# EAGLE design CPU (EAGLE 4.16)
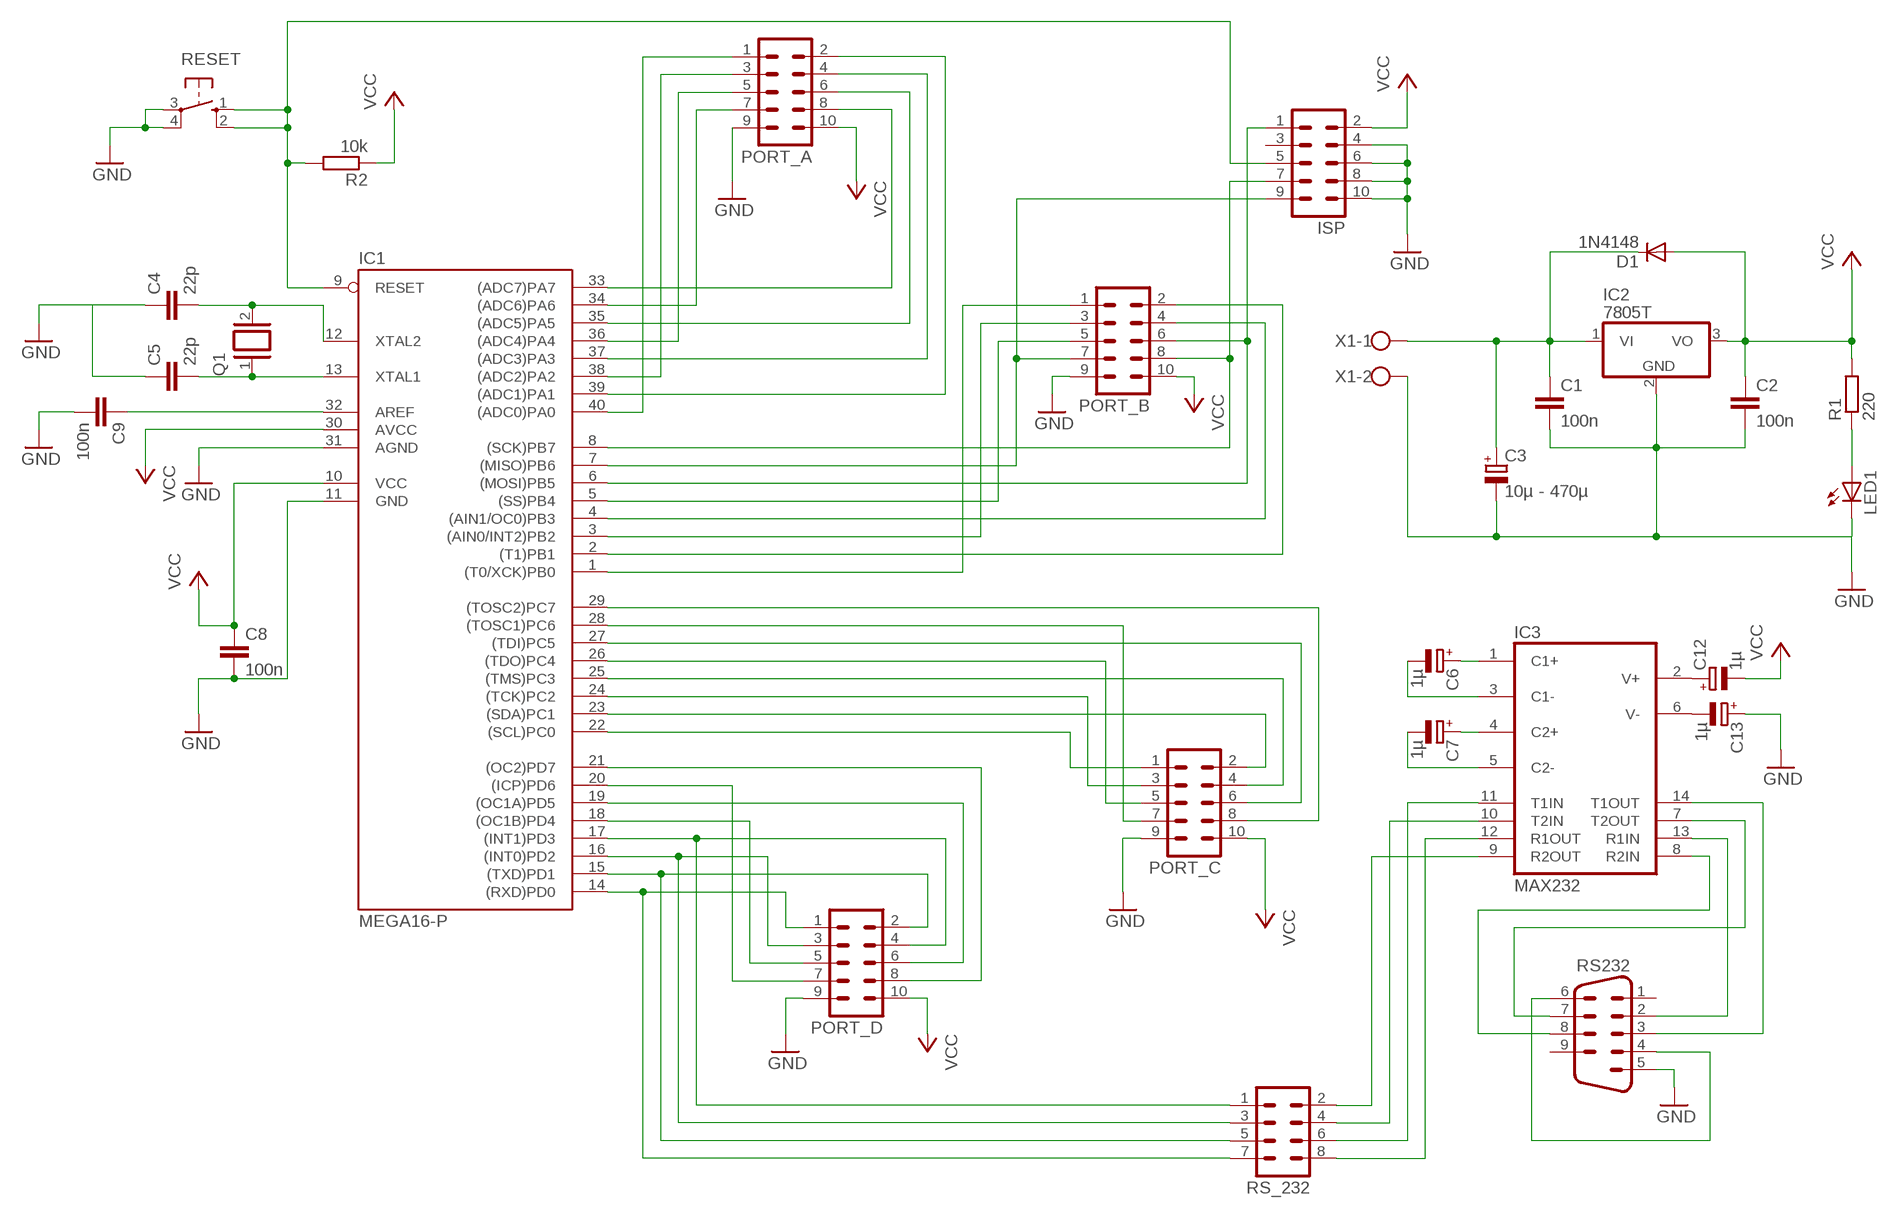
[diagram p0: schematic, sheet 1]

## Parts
C1  100n  C7.5/5  [C7.5B5]
C2  100n  C7.5/5  [C7.5B5]
C3  10µ - 470µ  CPOL-EUE5-10.5  [E5-10,5]
C4  22p  C5/3  [C5B3]
C5  22p  C5/3  [C5B3]
C6  1µ  CPOL-EUE3.5-8  [E3,5-8]
C7  1µ  CPOL-EUE3.5-8  [E3,5-8]
C8  100n  C2.5/4  [C2.5-4]
C9  100n  C5/3  [C5B3]
C12  1µ  CPOL-EUE3.5-8  [E3,5-8]
C13  1µ  CPOL-EUE3.5-8  [E3,5-8]
D1  1N4148  [DO35-10]
IC1  MEGA16-P  [DIL40]
IC2  7805T  [TO220H]
IC3  MAX232  [DIL16]
ISP  ML10  [ML10]
LED1  LED3MM  [LED3MM]
PORT_A  ML10  [ML10]
PORT_B  ML10  [ML10]
PORT_C  ML10  [ML10]
PORT_D  ML10  [ML10]
Q1  XTAL  [Q]
R1  220  R-EU_0207/10  [0207/10]
R2  10k  R-EU_0207/10  [0207/10]
RESET  10-XX  [B3F-10XX]
RS232  M09H  [M09H]
RS_232  MA04-2  [MA04-2]
X1  W237-102  [W237-102]

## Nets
GND: C1.2 C2.2 C3.- C4.1 C5.1 C8.2 C9.2 C13.+ IC1.11(GND) IC1.31(AGND) IC2.2(GND) ISP.4 ISP.6 ISP.8 ISP.10 LED1.K(C) PORT_A.9 PORT_B.9 PORT_C.9 PORT_D.9 RESET.3(P) RESET.4(P1) RS232.5 X1.2
ISP: IC1.7((MISO)PB6) ISP.9 PORT_B.7
N$1: C1.1 C3.+ D1.C IC2.1(VI) X1.1
N$5: LED1.A R1.1
N$6: IC1.40((ADC0)PA0) PORT_A.1
N$7: IC1.39((ADC1)PA1) PORT_A.2
N$8: IC1.37((ADC3)PA3) PORT_A.4
N$9: IC1.35((ADC5)PA5) PORT_A.6
N$10: IC1.33((ADC7)PA7) PORT_A.8
N$11: IC3.10(T2IN) RS_232.4
N$12: IC1.36((ADC4)PA4) PORT_A.5
N$13: IC1.34((ADC6)PA6) PORT_A.7
N$14: IC1.1((T0/XCK)PB0) PORT_B.1
N$15: IC1.2((T1)PB1) PORT_B.2
N$16: IC1.4((AIN1/OC0)PB3) PORT_B.4
N$17: IC1.6((MOSI)PB5) ISP.1 PORT_B.6
N$18: IC1.8((SCK)PB7) ISP.7 PORT_B.8
N$19: IC1.3((AIN0/INT2)PB2) PORT_B.3
N$20: IC1.5((SS)PB4) PORT_B.5
N$21: IC1.38((ADC2)PA2) PORT_A.3
N$22: IC1.22((SCL)PC0) PORT_C.1
N$23: IC1.23((SDA)PC1) PORT_C.2
N$24: IC1.24((TCK)PC2) PORT_C.3
N$25: IC1.25((TMS)PC3) PORT_C.4
N$26: IC1.26((TDO)PC4) PORT_C.5
N$27: IC1.27((TDI)PC5) PORT_C.6
N$28: IC1.28((TOSC1)PC6) PORT_C.7
N$29: IC1.29((TOSC2)PC7) PORT_C.8
N$30: IC1.14((RXD)PD0) PORT_D.1 RS_232.7
N$31: IC1.15((TXD)PD1) PORT_D.2 RS_232.5
N$32: IC1.16((INT0)PD2) PORT_D.3 RS_232.3
N$33: IC1.17((INT1)PD3) PORT_D.4 RS_232.1
N$34: IC1.18((OC1B)PD4) PORT_D.5
N$35: IC1.19((OC1A)PD5) PORT_D.6
N$36: IC1.20((ICP)PD6) PORT_D.7
N$37: IC1.21((OC2)PD7) PORT_D.8
N$38: IC3.9(R2OUT) RS_232.2
N$39: C5.2 IC1.13(XTAL1) Q1.1
N$40: C4.2 IC1.12(XTAL2) Q1.2
N$42: C12.+ IC3.2(V+)
N$43: C13.- IC3.6(V-)
N$44: RS232.4 RS232.6
N$45: IC3.12(R1OUT) RS_232.8
N$46: IC3.11(T1IN) RS_232.6
N$47: IC3.7(T2OUT) RS232.7
N$48: IC3.8(R2IN) RS232.8
N$49: IC1.9(RESET) ISP.5 R2.2 RESET.1(S) RESET.2(S1)
N$53: C9.1 IC1.32(AREF)
N$201: C6.- IC3.3(C1-)
N$202: C6.+ IC3.1(C1+)
N$203: C7.- IC3.5(C2-)
N$204: C7.+ IC3.4(C2+)
N$205: IC3.14(T1OUT) RS232.3
N$206: IC3.13(R1IN) RS232.2
VCC: C2.1 C8.1 C12.- D1.A IC1.10(VCC) IC1.30(AVCC) IC2.3(VO) ISP.2 PORT_A.10 PORT_B.10 PORT_C.10 PORT_D.10 R1.2 R2.1
Unconnected: ISP.3 RS232.1 RS232.9

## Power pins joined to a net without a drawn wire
GND: IC3.15(GND)
VCC: IC3.16(VCC)

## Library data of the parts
C1 C2 C4 C5 C8 C9 = capacitor-wima:C: CAPACITOR
C3 C6 C7 C12 C13 = rcl:CPOL-EU: POLARIZED CAPACITOR, European symbol
D1 = diode:1N4148: DIODE
IC1 = atmel:MEGA16-P: MICROCONTROLLER 16 Kbytes FLASH 1 kbytes SRAM 512 bytes EEPROM USART 8-channel 10 bit ADC Source: avr.lbr
IC2 = linear:78*: Positive VOLTAGE REGULATOR Source: http://cache.national.com/ds/LM/LM78L05.pdf http://www.fairchildsemi.com/ds/LM/LM7805.pdf
IC3 = maxim:MAX232: RS232 TRANSEIVER
ISP PORT_A PORT_B PORT_C PORT_D = con-harting-ml:ML10: HARTING
LED1 = led:LED: LED
Q1 = special:XTAL: CRYSTAL
R1 R2 = rcl:R-EU_: RESISTOR, European symbol
RESET = switch-omron:10-XX: OMRON SWITCH
RS232 = con-subd:M09: SUB-D
RS_232 = con-lstb:MA04-2: PIN HEADER
X1 = con-wago-500:W237-102: WAGO SCREW CLAMP

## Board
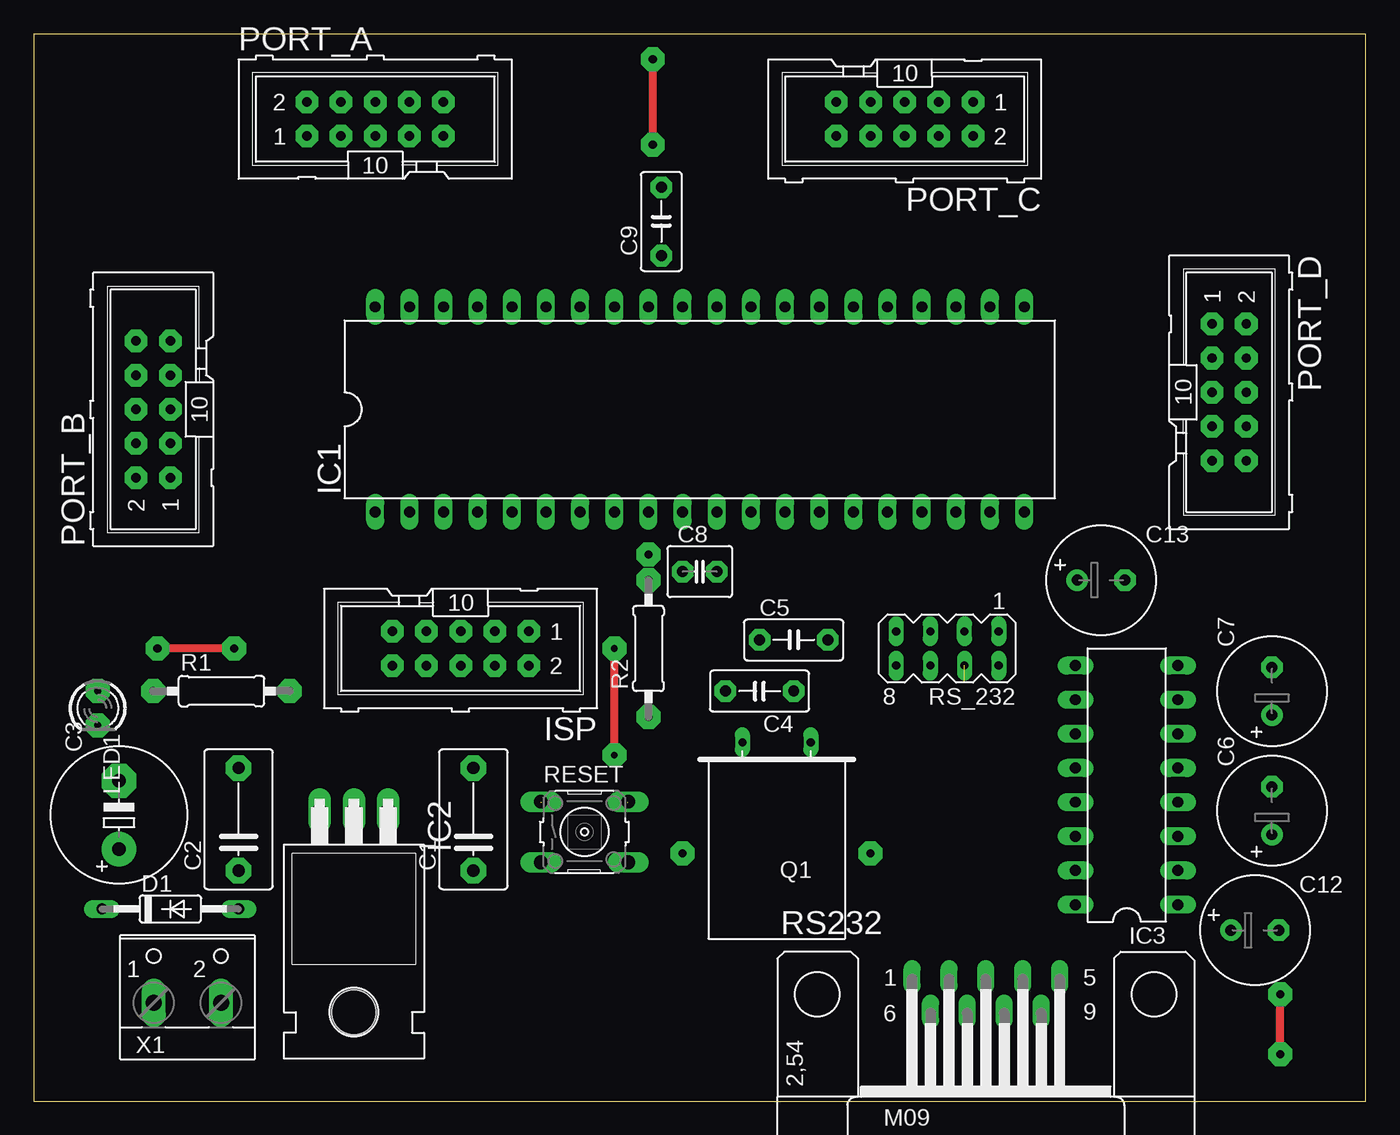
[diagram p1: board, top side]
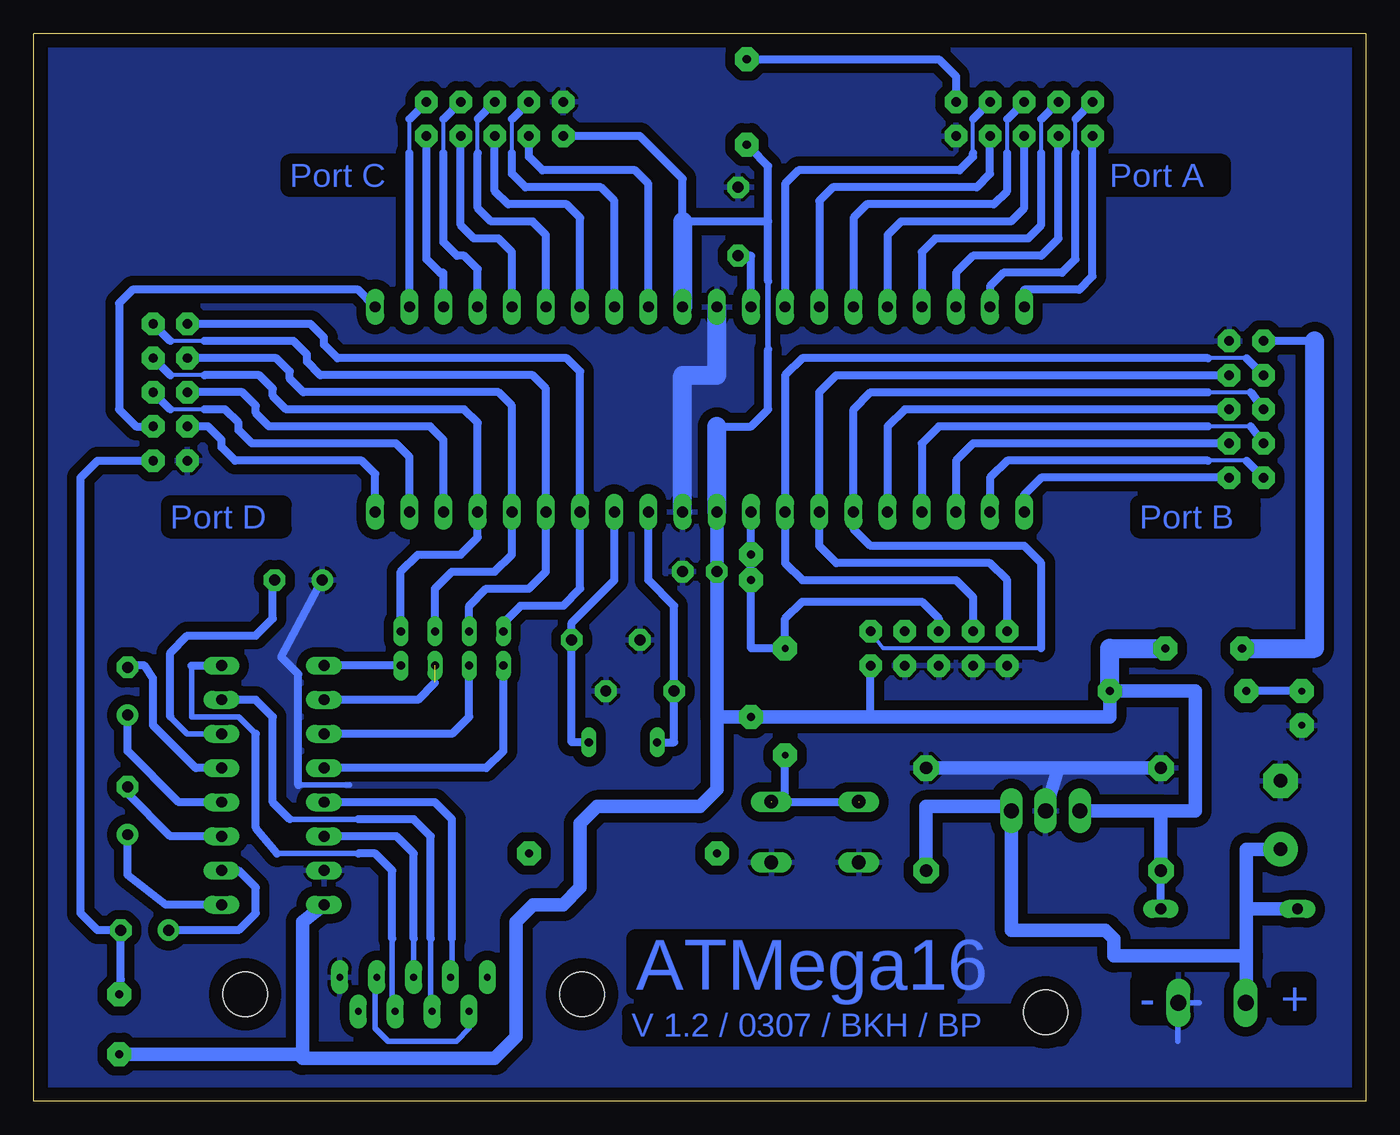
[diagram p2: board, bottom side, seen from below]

Size 99.06 x 79.38 mm. Coordinates in mm from the lower left corner, seen from the top.
Outline: 0,0 99.06,0 99.06,79.38 0,79.38 0,0
Copper layers (1*16): Top 0.035mm / dielectric 1.5mm / Bottom 0.035mm
Design rules "default": minimum track width 10mil, minimum drill 24mil, track to track 28mil, track to pad 28mil, pad to pad 10mil, via to via 10mil, smd to smd 8mil, copper to edge 40mil, drill to drill 8mil, minimum pad ring 10mil, minimum via ring 8mil, stop-mask expansion 4mil, vias tented up to drill 0mil, thermal gap 10mil

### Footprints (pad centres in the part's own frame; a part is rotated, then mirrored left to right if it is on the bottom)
C7.5B5 = drill 0.914 pad 1.905 octagon: 1 -3.81,0; 2 3.81,0
E5-10,5 = drill 1.016 pad 2.54 round: + -2.54,0 | drill 1.016 pad 2.54 octagon: - 2.54,0
C5B3 = drill 0.813 pad 1.6 octagon: 1 -2.54,0; 2 2.54,0
E3,5-8 = drill 0.813 pad 1.6 round: + -1.778,0 | drill 0.813 pad 1.6 octagon: - 1.778,0
C2.5-4 = drill 0.813 pad 1.6 octagon: 1 -1.27,0; 2 1.27,0
DO35-10 = drill 0.813 long: A 5.08,0; C -5.08,0
DIL40 = drill 0.813 long: 1 -24.13,-7.62; 2 -21.59,-7.62; 3 -19.05,-7.62; 4 -16.51,-7.62; 5 -13.97,-7.62; 6 -11.43,-7.62; 7 -8.89,-7.62; 8 -6.35,-7.62; 9 -3.81,-7.62; 10 -1.27,-7.62; 11 1.27,-7.62; 12 3.81,-7.62; 13 6.35,-7.62; 14 8.89,-7.62; 15 11.43,-7.62; 16 13.97,-7.62; 17 16.51,-7.62; 18 19.05,-7.62; 19 21.59,-7.62; 20 24.13,-7.62; 21 24.13,7.62; 22 21.59,7.62; 23 19.05,7.62; 24 16.51,7.62; 25 13.97,7.62; 26 11.43,7.62; 27 8.89,7.62; 28 6.35,7.62; 29 3.81,7.62; 30 1.27,7.62; 31 -1.27,7.62; 32 -3.81,7.62; 33 -6.35,7.62; 34 -8.89,7.62; 35 -11.43,7.62; 36 -13.97,7.62; 37 -16.51,7.62; 38 -19.05,7.62; 39 -21.59,7.62; 40 -24.13,7.62
TO220H = drill 1.118 long: 1 -2.54,-10.16; 2 0,-10.16; 3 2.54,-10.16 | hole 3.302: 0,4.826
DIL16 = drill 0.813 long: 1 -8.89,-3.81; 2 -6.35,-3.81; 3 -3.81,-3.81; 4 -1.27,-3.81; 5 1.27,-3.81; 6 3.81,-3.81; 7 6.35,-3.81; 8 8.89,-3.81; 9 8.89,3.81; 10 6.35,3.81; 11 3.81,3.81; 12 1.27,3.81; 13 -1.27,3.81; 14 -3.81,3.81; 15 -6.35,3.81; 16 -8.89,3.81
ML10 = drill 0.7 pad 1.676 octagon: 1 -5.08,-1.27; 2 -5.08,1.27; 3 -2.54,-1.27; 4 -2.54,1.27; 5 0,-1.27; 6 0,1.27; 7 2.54,-1.27; 8 2.54,1.27; 9 5.08,-1.27; 10 5.08,1.27
LED3MM = drill 0.5 pad 1.778 octagon: A -1.27,0; K 1.27,0
Q = drill 0.61 long: 1 -2.54,-7.62; 2 2.54,-7.62
0207/10 = drill 0.6 pad 1.778 octagon: 1 -5.08,0; 2 5.08,0
B3F-10XX = drill 1.016 long: 1 -3.251,2.261; 2 3.251,2.261; 3 -3.251,-2.261; 4 3.251,-2.261
M09H = drill 0.5 pad 1.27 long: 1 -5.486,1.27; 2 -2.743,1.27; 3 0,1.27; 4 2.743,1.27; 5 5.486,1.27; 6 -4.115,-1.27; 7 -1.372,-1.27; 8 1.372,-1.27; 9 4.115,-1.27 | hole 3.302: 12.522,0; -12.522,0
MA04-2 = drill 0.6 long: 1 -3.81,-1.27; 2 -3.81,1.27; 3 -1.27,-1.27; 4 -1.27,1.27; 5 1.27,-1.27; 6 1.27,1.27; 7 3.81,-1.27; 8 3.81,1.27
W237-102 = drill 1.194 long: 1 -2.5,-1.27; 2 2.5,-1.27

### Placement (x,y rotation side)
C1  32.7,20.95 90 top
C2  15.24,20.95 90 top
C3  6.35,21.27 90 top
C4  53.98,30.48 180 top
C5  56.52,34.29 0 top
C6  92.08,21.59 90 top
C7  92.08,30.48 90 top
C8  49.53,39.37 0 top
C9  46.67,65.41 90 top
C12  90.81,12.7 0 top
C13  79.38,38.73 0 top
D1  10.16,14.29 0 top
IC1  49.53,51.44 0 top
IC2  23.81,11.43 180 top
IC3  81.28,23.5 90 top
ISP  31.75,33.66 180 top
LED1  4.76,29.21 270 top
PORT_A  25.4,73.03 0 top
PORT_B  8.89,51.44 90 top
PORT_C  64.77,73.03 180 top
PORT_D  88.9,52.7 270 top
Q1  55.24,19.05 180 top
R1  13.97,30.48 0 top
R2  45.72,33.66 90 top
RESET  40.96,20 0 top
RS232  70.8,7.94 0 top
RS_232  67.94,33.66 180 top
X1  11.43,8.57 0 top

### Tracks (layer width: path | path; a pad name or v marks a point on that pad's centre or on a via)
GND
  Bottom 0.406: 75.56,23.5 79.38,23.5 | 12.38,7.3 X1.2 13.97,7.3 13.97,4.45
  Bottom 0.61: C13.+ 80.64,33.02 79.38,31.75 79.38,23.5
  Bottom 1.016: 22.86,24.77 IC2.2 | 22.86,24.77 C1.2 | C2.2 22.86,24.77
  Bottom 1.422: IC1.31 48.26,53.98 50.8,53.98 IC1.11
  pour Bottom: 0,0.95 98.11,0.95 98.11,81.6 0,81.6
ISP
  Bottom 0.61: ISP.9 26.67,38.73 27.94,40.01 39.37,40.01 40.64,41.27 IC1.7 40.64,52.7 39.37,53.98 PORT_B.7
N$1
  Bottom 1.016: C1.1 32.7,21.91 26.67,21.91 IC2.1 26.35,12.7 19.37,12.7 18.73,12.06 18.73,10.79 8.89,10.79 | C3.+ 8.89,18.73 8.89,14.29 | 8.89,10.79 8.89,14.29 | X1.1 8.89,7.34 8.89,10.79 | 8.89,14.29 D1.C
N$3  (via drill 0.5 pad 1.78)
  other vias: 43.18,25.72
N$4  (via drill 0.6 pad 1.78)
  other vias: 48.26,18.41
N$5
  Bottom 0.61: LED1.A R1.1
N$6
  Bottom 0.61: PORT_A.1 20.32,61.33 21.32,60.33 25.4,60.33 IC1.40
N$7
  Bottom 0.305: 21.59,70.48 21.59,73.03
  Bottom 0.61: 21.59,73.03 PORT_A.2 | 21.59,70.48 21.59,62.59 22.59,61.59 26.94,61.59 27.94,60.59 IC1.39
N$8
  Bottom 0.305: 24.13,70.48 24.13,73.03
  Bottom 0.61: 24.13,73.03 PORT_A.4 | 24.13,70.48 24.13,65.14 25.13,64.14 32.02,64.14 33.02,63.13 IC1.37
N$9
  Bottom 0.305: 26.67,70.48 26.67,73.03
  Bottom 0.61: 26.67,73.03 PORT_A.6 | 26.67,70.48 26.67,67.67 27.67,66.67 37.1,66.67 38.1,65.67 IC1.35
N$10
  Bottom 0.305: 29.21,70.48 29.21,73.03
  Bottom 0.61: 29.21,73.03 PORT_A.8 | 29.21,70.48 29.21,70.22 30.21,69.22 42.18,69.22 43.18,68.22 IC1.33
N$11  (1 unrouted)
  Bottom 0.61: 69.22,31.11 70.48,29.84 IC3.10
N$12
  Bottom 0.61: PORT_A.5 25.4,66.41 26.4,65.41 34.56,65.41 35.56,64.41 IC1.36
N$13
  Bottom 0.61: PORT_A.7 27.94,68.94 28.94,67.94 39.64,67.94 40.64,66.94 IC1.34
N$14
  Bottom 0.61: PORT_B.1 24.13,46.35 25.4,45.09 IC1.1
N$15
  Bottom 0.305: 8.89,47.62 11.75,47.62
  Bottom 0.61: PORT_B.2 8.89,47.62 | IC1.2 27.94,46.35 26.67,47.62 11.75,47.62
N$16
  Bottom 0.305: 8.57,50.16 11.75,50.16
  Bottom 0.61: PORT_B.4 8.57,50.16 | IC1.4 33.02,48.9 31.75,50.16 11.75,50.16
N$17
  Bottom 0.305: 11.75,52.7 8.57,52.7 | 24.13,33.66 35.88,33.66 ISP.1
  Bottom 0.61: 8.57,52.7 PORT_B.6 | 24.13,33.66 24.13,40.01 25.4,41.27 36.83,41.27 38.1,42.55 IC1.6 38.1,51.44 36.83,52.7 11.75,52.7
N$18
  Bottom 0.305: 8.89,55.24 11.75,55.24
  Bottom 0.61: PORT_B.8 8.89,55.24 | ISP.7 29.21,37.47 30.48,38.73 41.91,38.73 43.18,40.01 IC1.8 43.18,53.98 41.91,55.24 11.75,55.24
N$19
  Bottom 0.61: IC1.3 30.48,47.62 29.21,48.9 PORT_B.3
N$20
  Bottom 0.61: IC1.5 35.56,50.16 34.29,51.44 PORT_B.5
N$21
  Bottom 0.61: IC1.38 30.48,61.59 29.21,62.87 24.13,62.87 22.86,64.14 PORT_A.3
N$22
  Bottom 0.305: 71.12,70.48 71.12,73.03
  Bottom 0.61: IC1.22 71.12,70.48 | 71.12,73.03 PORT_C.1
N$23
  Bottom 0.61: IC1.23 68.58,61.59 68.85,61.59 69.85,62.59 PORT_C.2
N$24
  Bottom 0.305: 68.58,70.48 68.58,73.03
  Bottom 0.61: IC1.24 66.04,61.87 67.04,62.87 67.58,62.87 68.58,63.87 68.58,70.48 | 68.58,73.03 PORT_C.3
N$25
  Bottom 0.61: IC1.25 63.5,63.13 64.5,64.14 66.31,64.14 67.31,65.14 PORT_C.4
N$26
  Bottom 0.305: 66.04,70.48 66.04,73.03
  Bottom 0.61: IC1.26 60.96,64.41 61.96,65.41 65.04,65.41 66.04,66.41 66.04,70.48 | 66.04,73.03 PORT_C.5
N$27
  Bottom 0.61: IC1.27 58.42,65.67 59.42,66.67 63.77,66.67 64.77,67.67 PORT_C.6
N$28
  Bottom 0.305: 63.5,70.48 63.5,73.03
  Bottom 0.61: IC1.28 55.88,66.94 56.88,67.94 62.5,67.94 63.5,68.94 63.5,70.48 | 63.5,73.03 PORT_C.7
N$29
  Bottom 0.61: IC1.29 53.34,68.22 54.34,69.22 61.23,69.22 62.23,70.22 PORT_C.8
N$30
  Bottom 0.61: PORT_D.1 78.47,57.78 77.47,56.78 77.47,56.24 76.47,55.24 59.42,55.24 58.42,54.24 IC1.14 58.42,38.1 59.69,36.83 62.87,36.83 64.14,35.56 RS_232.7
N$31
  Bottom 0.305: 86.36,56.52 88.9,56.52
  Bottom 0.61: 86.36,56.52 79.74,56.52 78.74,55.52 78.74,54.98 77.74,53.98 61.96,53.98 60.96,52.98 IC1.15 60.96,39.37 62.23,38.1 65.41,38.1 66.67,36.83 RS_232.5 | 88.9,56.52 PORT_D.2
N$32
  Bottom 0.61: PORT_D.3 81.01,55.24 80.01,54.24 80.01,53.7 79.01,52.7 64.5,52.7 63.5,51.7 IC1.16 63.5,40.64 64.77,39.37 67.94,39.37 69.22,38.1 RS_232.3
N$33
  Bottom 0.305: 86.36,53.98 88.9,53.98
  Bottom 0.61: 86.36,53.98 82.28,53.98 81.28,52.98 81.28,52.44 80.28,51.44 67.04,51.44 66.04,50.44 IC1.17 66.04,41.91 67.31,40.64 70.48,40.64 71.75,39.37 RS_232.1 | 88.9,53.98 PORT_D.4
N$34
  Bottom 0.61: IC1.18 68.58,49.16 69.58,50.16 81.55,50.16 82.55,51.16 82.55,51.7 83.55,52.7 PORT_D.5
N$35
  Bottom 0.305: 86.36,51.44 88.9,51.44
  Bottom 0.61: IC1.19 71.12,47.9 72.12,48.9 82.82,48.9 83.82,49.9 83.82,50.44 84.82,51.44 86.36,51.44 | 88.9,51.44 PORT_D.6
N$36
  Bottom 0.61: IC1.20 73.66,46.62 74.66,47.62 84.09,47.62 85.09,48.62 85.09,49.16 86.09,50.16 PORT_D.7
N$37
  Bottom 0.61: IC1.21 74.93,60.33 91.71,60.33 92.71,59.33 92.71,51.44 91.44,50.16 PORT_D.8
N$38
  Bottom 0.61: RS_232.2 IC3.9
N$39
  Bottom 0.61: Q1.1 59.05,26.67 C5.2 59.05,35.56 55.88,38.73 IC1.13
N$40
  Bottom 0.61: Q1.2 51.44,26.67 C4.2 51.44,36.83 53.34,38.73 IC1.12
N$41  (via drill 0.6 pad 1.78)
  other vias: 62.23,18.41
N$42
  Bottom 0.61: IC3.2 83.82,17.14 82.55,15.88 82.55,13.97 83.82,12.7 C12.+
N$43
  Bottom 0.406: IC3.6 87.63,27.3 88.9,28.57
  Bottom 0.61: 88.9,28.57 88.9,33.34 87.63,34.61 82.55,34.61 81.28,35.88 81.28,38.73 C13.-
N$44
  Bottom 0.406: 73.66,9.09 73.66,5.4 72.71,4.45 67.63,4.45 66.67,5.4 66.67,6.67
  Bottom 0.61: 73.66,9.09 RS232.4 | 66.67,6.67 RS232.6
N$45
  Bottom 0.61: IC3.12 65.41,24.77 64.14,26.04 RS_232.8
N$46
  Bottom 0.61: RS_232.6 66.67,28.57 67.94,27.3 IC3.11
N$47
  Bottom 0.406: 74.93,20.95 80.01,20.95 | 69.53,6.67 69.53,12.06
  Bottom 0.61: 74.93,20.95 70.8,20.95 69.53,19.68 69.53,12.06 | 80.01,20.95 81.28,22.23 81.28,28.57 82.55,29.84 IC3.7 | RS232.7 69.53,6.67
N$48
  Bottom 0.406: 87.31,32.38 87.31,28.57 83.82,28.57 82.55,27.3 | 74.93,18.41 80.96,18.41 | 72.39,6.67 72.39,12.06
  Bottom 0.61: 87.31,32.38 IC3.8 | 82.55,27.3 82.55,20.32 80.96,18.41 | 74.93,18.41 73.66,18.41 72.39,17.14 72.39,12.06 | RS232.8 72.39,6.67
N$49  (via drill 0.5 pad 1.78, 0.6 pad 1.78)  (2 unrouted)
  Top 0.61: v43.18,25.72 v43.18,33.66
  Bottom 0.61: ISP.5 31.75,35.88 33.02,37.15 41.91,37.15 43.18,35.88 v43.18,33.66 45.72,33.66 R2.2 v45.72,40.64 IC1.9 | 43.18,22.23 v43.18,25.72 | 43.18,22.23 44.17,22.23 | 37.74,22.23 43.18,22.23
N$53
  Bottom 0.61: IC1.32 45.72,62.87 C9.1
N$201
  Bottom 0.61: IC3.3 88.9,19.68 92.08,22.86 C6.- 92.08,23.5
N$202
  Bottom 0.61: IC3.1 89.22,14.61 92.08,16.83 C6.+
N$203
  Bottom 0.61: C7.- 92.08,32.38 90.81,32.38 90.17,31.43 90.17,27.94 87,24.77 IC3.5
N$204
  Bottom 0.61: IC3.4 88.27,22.23 92.08,26.04 C7.+
N$205
  Bottom 0.406: RS232.3 70.8,12.06
  Bottom 0.61: RS232.3 70.48,9.21 | IC3.14 72.07,19.68 70.8,18.41 70.8,12.06
N$206
  Bottom 0.406: 67.94,9.21 67.94,12.06
  Bottom 0.61: IC3.13 69.22,22.23 67.94,20.95 67.94,12.06 | RS232.2 67.94,9.21
VCC  (via drill 0.6 pad 1.78)
  Top 0.61: v14.92,33.66 v9.21,33.66 | v92.71,3.49 v92.71,7.94 | v46.04,71.12 v46.04,77.47
  Bottom 0.406: 44.45,55.88 44.45,60.96 | 79.06,3.17 79.06,3.49
  Bottom 0.61: C8.1 IC1.10 | D1.A C2.1 | 48.26,50.16 45.72,50.16 44.45,51.44 44.45,55.88 | 44.45,60.96 44.45,65.41 | 44.45,65.41 50.8,65.41 50.8,68.58 53.98,71.75 PORT_C.10 | 3.81,56.52 PORT_B.10 | C12.- 92.71,12.7 | 36.83,28.57 ISP.2 | C12.- 92.58,9.02 v92.71,7.94 | C12.- 94.3,12.7 95.57,13.97 95.57,46.35 94.3,47.62 PORT_D.10 | v46.04,77.47 31.75,77.47 30.48,76.2 PORT_A.10 | v46.04,71.12 46.04,70.8 45.72,70.8 44.45,69.53 44.45,65.41
  Bottom 1.016: C2.1 15.24,21.59 IC2.3 12.7,21.59 12.7,28.57 | 48.26,28.57 C8.1 IC1.10 | 48.26,28.57 R2.1 36.83,28.57 19.05,28.57 R1.2 12.7,30.48 12.7,28.57 | 12.7,28.57 12.7,29.21 | IC3.16 79.06,13.34 79.06,3.49 v92.71,3.49 | 79.06,3.17 64.77,3.17 63.18,4.76 63.18,13.34 61.91,14.61 59.69,14.61 58.42,15.88 58.42,20.64 57.15,21.91 49.53,21.91 48.26,23.18 48.26,28.57
  Bottom 1.422: 50.8,65.41 IC1.30 | IC1.10 48.26,50.16 | 3.81,56.52 3.81,33.66 v9.21,33.66 | v14.92,33.66 19.05,33.66 R1.2

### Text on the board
Bottom: Port A | Port C | Port B | Port D | ATMega16 | + | - | V 1.2 / 0307 / BKH / BP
